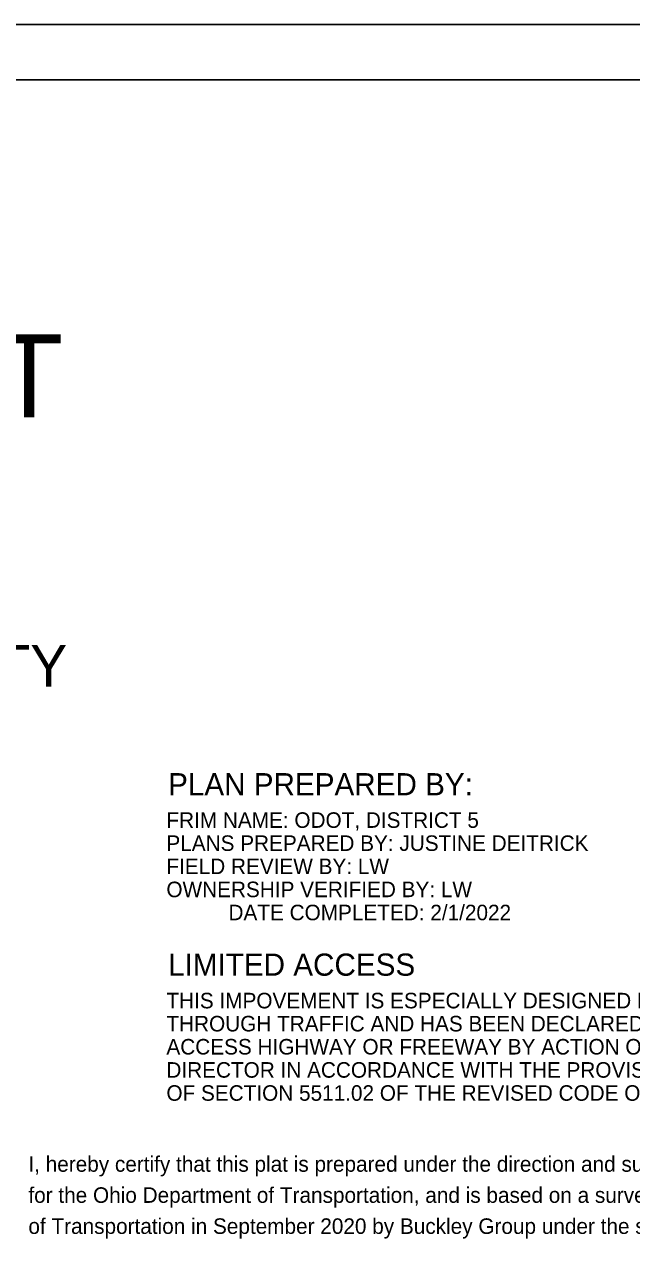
# Model space of a CAD drawing. Extents: x 0 to 34, y 0 to 22.
# Drawn here: x 19.88 to 25.36, y 11.01 to 22 of the extents above; entities that cross this region are included whole.
import ezdxf

# ---------------------------------------------------------------- set-up
doc = ezdxf.new("R2010")
doc.units = 0
for name, color, linetype in [('SH_Border', 7, 'Continuous'), ('SH_Cut_Line', 7, 'Continuous'), ('SH_Text', 7, 'Continuous')]:
    doc.layers.add(name, color=color, linetype=linetype)

msp = doc.modelspace()

# ---------------------------------------------------------------- linework, layer by layer
at = {"layer": 'SH_Border'}
msp.add_lwpolyline([(2, 21.5), (33.5, 21.5), (33.5, 0.5), (2, 0.5)], close=True, dxfattribs=at)
at = {"layer": 'SH_Cut_Line'}
msp.add_lwpolyline([(0, 0), (34, 0), (34, 22), (0, 22)], close=True, dxfattribs=at)

# ---------------------------------------------------------------- texts
at = {"layer": 'SH_Text'}
for s, height, p in [('LEGEND SHEET', 0.75, (12.48, 18.457)), ('MUSKINGUM COUNTY', 0.375, (14.888, 16.032)), ('PLAN PREPARED BY:', 0.2, (21.174, 15.051)), ('FRIM NAME: ODOT, DISTRICT 5', 0.14, (21.159, 14.758)), ('PLANS PREPARED BY: JUSTINE DEITRICK', 0.14, (21.159, 14.55)), ('FIELD REVIEW BY: LW ', 0.14, (21.159, 14.341)), ('OWNERSHIP VERIFIED BY: LW', 0.14, (21.159, 14.133)), ('DATE COMPLETED: 2/1/2022', 0.14, (21.719, 13.925)), ('LIMITED ACCESS', 0.2, (21.174, 13.425)), ('THIS IMPOVEMENT IS ESPECIALLY DESIGNED FOR', 0.14, (21.159, 13.131)), ('THROUGH TRAFFIC AND HAS BEEN DECLARED A LIMITED', 0.14, (21.159, 12.923)), ('ACCESS HIGHWAY OR FREEWAY BY ACTION OF THE', 0.14, (21.159, 12.715)), ('DIRECTOR IN ACCORDANCE WITH THE PROVISIONS', 0.14, (21.159, 12.506)), ('OF SECTION 5511.02 OF THE REVISED CODE OF OHIO.', 0.14, (21.159, 12.298)), ('I, hereby certify that this plat is prepared under the direction and supervision of Luke Walker, P.S. #8701 ', 0.140014, (19.914, 11.658)), ('for the Ohio Department of Transportation, and is based on a survey performed for the Ohio Department ', 0.140014, (19.914, 11.378)), ('of Transportation in September 2020 by Buckley Group under the supervision of Robert C. Canter, P.S. ', 0.140014, (19.914, 11.098))]:
    msp.add_text(s, height=height, dxfattribs=at).set_placement(p)

doc.saveas('drawing.dxf')
